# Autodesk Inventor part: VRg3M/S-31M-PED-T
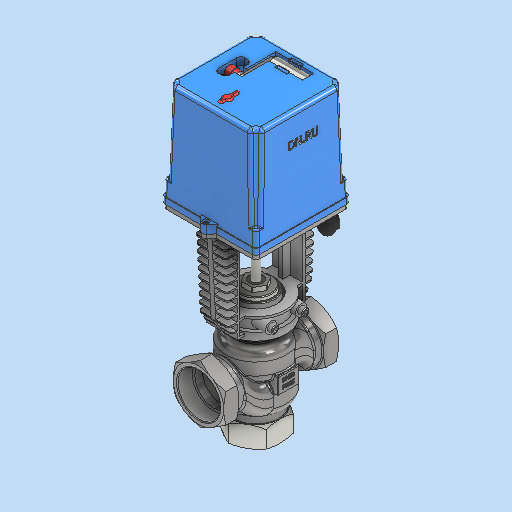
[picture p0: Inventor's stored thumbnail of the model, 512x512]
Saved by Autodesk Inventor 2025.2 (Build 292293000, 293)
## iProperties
Created: 2026-04
Part Number: VRg3M/S-31M-PED-T
Material: Типовые
Description: D230-11268
Document SubType Name: Modeling
Designer: DN.RU
Mass: 4600 g
Surface Area: 2641.27 cm^2
Volume: 2894.5 cm^3
Density: 1.58922 g/cm^3
Appearance: По умолчанию
Company: DN.RU
Title: Клапан регулирующий трехходовой Ду50 Ру25
Author: DN.RU
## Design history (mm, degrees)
derived "Сборка.iam"
node "Твердое тело1"
node "Деталь 1.ipt:1"
node "Деталь 2.ipt:1"
node "Деталь 3.ipt:1"
node "AS 1420 - метрическая M5 x 10:1"
node "AS 1420 - метрическая M5 x 10:2"
node "AS 1427 H - метрическая M3 x 8:1"
node "AS 1427 H - метрическая M3 x 8:2"
node "AS 1421 засверленный конец - метрическая M10 x 12 засверленн"
node "AS 1421 засверленный конец - метрическая M10 x 12 засверленн"
